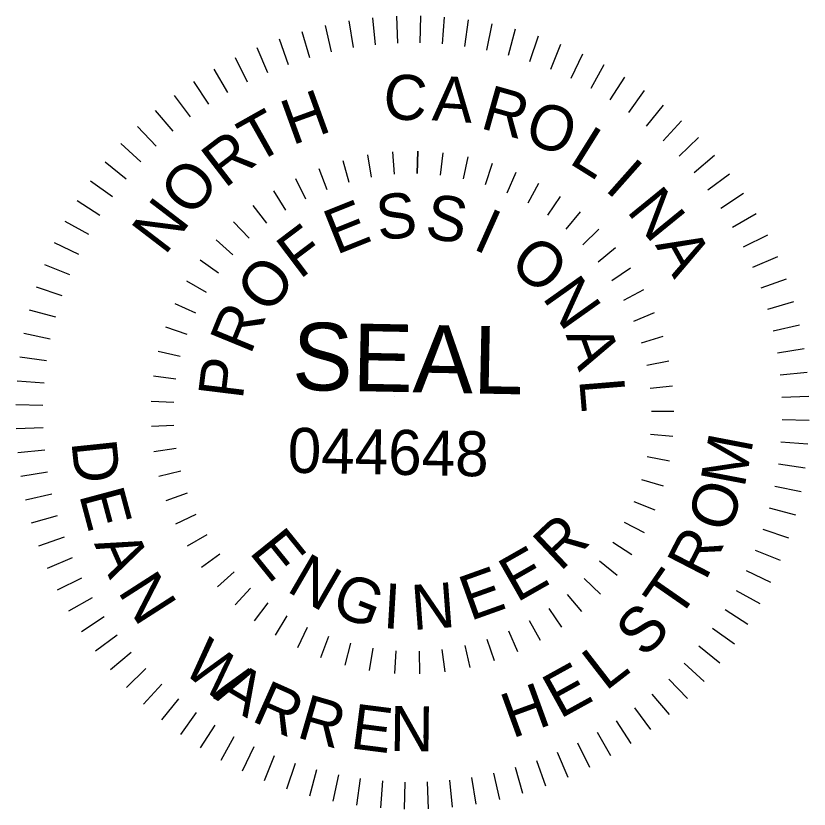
# Model space of a CAD drawing. Extents: x 0 to 2694, y -754 to 1499.
# Drawn here: x 3.3291 to 3.4509, y 1.8873 to 2.009 of the extents above; entities that cross this region are included whole.
import ezdxf

# ---------------------------------------------------------------- set-up
doc = ezdxf.new("R2010")
doc.units = 0
doc.layers.add('UBO Plan Sheet 34 CELL', color=7, linetype='Continuous')

msp = doc.modelspace()

# ---------------------------------------------------------------- linework, layer by layer
at = {"layer": 'UBO Plan Sheet 34 CELL'}
for p, q in [((3.38021, 2.00827), (3.38088, 2.00418)), ((3.38386, 2.00875), (3.38427, 2.00462)), ((3.38752, 2.00901), (3.38769, 2.00486)), ((3.3912, 2.00905), (3.39112, 2.0049)), ((3.39488, 2.00886), (3.39455, 2.00473)), ((3.39853, 2.00846), (3.39795, 2.00435)), ((3.37661, 2.00757), (3.37751, 2.00352)), ((3.40215, 2.00784), (3.40133, 2.00377)), ((3.40573, 2.00699), (3.40466, 2.00298)), ((3.37304, 2.00665), (3.3742, 2.00266)), ((3.40926, 2.00594), (3.40794, 2.00199)), ((3.36955, 2.00552), (3.37094, 2.00161)), ((3.4127, 2.00467), (3.41115, 2.00082)), ((3.36612, 2.00418), (3.36775, 2.00036)), ((3.36278, 2.00264), (3.36464, 1.99892)), ((3.41607, 2.00319), (3.4143, 1.99944)), ((3.41935, 2.00152), (3.41734, 1.99788)), ((3.35954, 2.00089), (3.36162, 1.9973)), ((3.35642, 1.99896), (3.35871, 1.9955)), ((3.42251, 1.99965), (3.42029, 1.99614)), ((3.42556, 1.99759), (3.42314, 1.99422)), ((3.35342, 1.99684), (3.35591, 1.99353)), ((3.42847, 1.99535), (3.42585, 1.99214)), ((3.35054, 1.99454), (3.35323, 1.99138)), ((3.43125, 1.99294), (3.42844, 1.98989)), ((3.34782, 1.99207), (3.35069, 1.98908)), ((3.43388, 1.99037), (3.43089, 1.9875)), ((3.34525, 1.98945), (3.34829, 1.98664)), ((3.38307, 1.98771), (3.38366, 1.9843)), ((3.38691, 1.98819), (3.38718, 1.98474)), ((3.39079, 1.9883), (3.39072, 1.98485)), ((3.39072, 1.98485), (3.39079, 1.9883)), ((3.39466, 1.98803), (3.39426, 1.9846)), ((3.43635, 1.98764), (3.43319, 1.98496)), ((3.34283, 1.98667), (3.34605, 1.98405)), ((3.37929, 1.98686), (3.38021, 1.98352)), ((3.39848, 1.9874), (3.39775, 1.98402)), ((3.40222, 1.9864), (3.40117, 1.9831)), ((3.37561, 1.98564), (3.37685, 1.98241)), ((3.37206, 1.98408), (3.3736, 1.98098)), ((3.40586, 1.98504), (3.40449, 1.98186)), ((3.43865, 1.98477), (3.43533, 1.98228)), ((3.3406, 1.98376), (3.34396, 1.98133)), ((3.40934, 1.98334), (3.40768, 1.98031)), ((3.36868, 1.98218), (3.37052, 1.97924)), ((3.44076, 1.98177), (3.43731, 1.97948)), ((3.33854, 1.98071), (3.34205, 1.97849)), ((3.41264, 1.98131), (3.41069, 1.97845)), ((3.3655, 1.97996), (3.36761, 1.97722)), ((3.41573, 1.97897), (3.41351, 1.97631)), ((3.4427, 1.97865), (3.43911, 1.97656)), ((3.33667, 1.97754), (3.34031, 1.97554)), ((3.36255, 1.97745), (3.36492, 1.97492)), ((3.41858, 1.97634), (3.41611, 1.97391)), ((3.44444, 1.9754), (3.44073, 1.97355)), ((3.335, 1.97426), (3.33875, 1.97249)), ((3.35985, 1.97466), (3.36245, 1.97238)), ((3.42116, 1.97345), (3.41848, 1.97127)), ((3.44598, 1.97207), (3.44217, 1.97044)), ((3.33352, 1.9709), (3.33737, 1.96935)), ((3.35744, 1.97163), (3.36024, 1.96961)), ((3.42346, 1.97032), (3.42058, 1.96841)), ((3.35533, 1.96838), (3.35832, 1.96663)), ((3.44733, 1.96864), (3.44342, 1.96725)), ((3.33225, 1.96745), (3.3362, 1.96614)), ((3.42543, 1.96699), (3.42238, 1.96537)), ((3.35354, 1.96494), (3.35668, 1.9635)), ((3.44846, 1.96515), (3.44447, 1.96399)), ((3.3312, 1.96392), (3.3352, 1.96286)), ((3.42709, 1.96348), (3.42389, 1.96216)), ((3.3521, 1.96134), (3.35537, 1.96021)), ((3.44937, 1.96158), (3.44533, 1.96068)), ((3.33035, 1.96035), (3.33442, 1.95952)), ((3.42839, 1.95983), (3.42507, 1.95883)), ((3.351, 1.95762), (3.35437, 1.95681)), ((3.45007, 1.95797), (3.44598, 1.95731)), ((3.32973, 1.95672), (3.33384, 1.95615)), ((3.42933, 1.95607), (3.42594, 1.95539)), ((3.35028, 1.95381), (3.3537, 1.95334)), ((3.45055, 1.95433), (3.44643, 1.95391)), ((3.32933, 1.95307), (3.33346, 1.95274)), ((3.42991, 1.95224), (3.42647, 1.95189)), ((3.34992, 1.94995), (3.35337, 1.9498)), ((3.38716, 1.95059), (3.38716, 1.95059)), ((3.45081, 1.95066), (3.44667, 1.9505)), ((3.32914, 1.9494), (3.33329, 1.94932)), ((3.43011, 1.94837), (3.42666, 1.94835)), ((3.34993, 1.94608), (3.35338, 1.94626)), ((3.45085, 1.94699), (3.4467, 1.94707)), ((3.32918, 1.94572), (3.33332, 1.94589)), ((3.42994, 1.94449), (3.4265, 1.94481)), ((3.35033, 1.94222), (3.35374, 1.94274)), ((3.45067, 1.94331), (3.44653, 1.94364)), ((3.32944, 1.94205), (3.33357, 1.94247)), ((3.42602, 1.94143), (3.42942, 1.94078)), ((3.45026, 1.93966), (3.44616, 1.94024)), ((3.32992, 1.93841), (3.33401, 1.93907)), ((3.35109, 1.93842), (3.35444, 1.93926)), ((3.42849, 1.93688), (3.42517, 1.93786)), ((3.44964, 1.93604), (3.44558, 1.93686)), ((3.33062, 1.9348), (3.33467, 1.93571)), ((3.35221, 1.93471), (3.35547, 1.93587)), ((3.42722, 1.93322), (3.42401, 1.93451)), ((3.4488, 1.93246), (3.44479, 1.93353)), ((3.33153, 1.93124), (3.33553, 1.93239)), ((3.35369, 1.93113), (3.35682, 1.9326)), ((3.42559, 1.92971), (3.42253, 1.9313)), ((3.33267, 1.92774), (3.33658, 1.92914)), ((3.3555, 1.92771), (3.35848, 1.92947)), ((3.44774, 1.92893), (3.4438, 1.93025)), ((3.42365, 1.92636), (3.42075, 1.92823)), ((3.44647, 1.92549), (3.44262, 1.92704)), ((3.33401, 1.92432), (3.33782, 1.92594)), ((3.35764, 1.92447), (3.36043, 1.92651)), ((3.42139, 1.9232), (3.41868, 1.92536)), ((3.36009, 1.92146), (3.36266, 1.92376)), ((3.44499, 1.92212), (3.44125, 1.92389)), ((3.33555, 1.92098), (3.33926, 1.92283)), ((3.41882, 1.9203), (3.41634, 1.9227)), ((3.3628, 1.9187), (3.36515, 1.92124)), ((3.44332, 1.91884), (3.43969, 1.92084)), ((3.33729, 1.91774), (3.34088, 1.91982)), ((3.416, 1.91764), (3.41376, 1.92028)), ((3.36578, 1.91621), (3.36786, 1.91897)), ((3.36898, 1.91402), (3.37079, 1.91697)), ((3.41293, 1.91528), (3.41095, 1.91811)), ((3.44145, 1.91567), (3.43795, 1.9179)), ((3.33923, 1.91461), (3.34269, 1.9169)), ((3.40965, 1.91322), (3.40795, 1.91623)), ((3.37238, 1.91216), (3.3739, 1.91526)), ((3.40618, 1.91149), (3.40478, 1.91465)), ((3.43939, 1.91263), (3.43603, 1.91505)), ((3.34135, 1.91161), (3.34466, 1.9141)), ((3.37594, 1.91062), (3.37715, 1.91386)), ((3.40256, 1.91009), (3.40147, 1.91338)), ((3.3805, 1.91278), (3.3796, 1.90944)), ((3.39882, 1.90906), (3.39806, 1.91244)), ((3.43716, 1.90972), (3.43394, 1.91233)), ((3.34365, 1.90874), (3.34681, 1.91143)), ((3.38342, 1.90862), (3.38398, 1.91203)), ((3.38727, 1.90817), (3.3875, 1.91162)), ((3.39114, 1.90809), (3.39105, 1.91155)), ((3.395, 1.90839), (3.39457, 1.91182)), ((3.43475, 1.90693), (3.4317, 1.90975)), ((3.34611, 1.90602), (3.3491, 1.90889)), ((3.43217, 1.90431), (3.4293, 1.9073)), ((3.34874, 1.90344), (3.35155, 1.90649)), ((3.42945, 1.90184), (3.42676, 1.905)), ((3.35152, 1.90103), (3.35414, 1.90424)), ((3.42657, 1.89954), (3.42409, 1.90286)), ((3.35443, 1.89879), (3.35686, 1.90216)), ((3.35748, 1.89674), (3.3597, 1.90024)), ((3.42357, 1.89742), (3.42129, 1.90088)), ((3.42045, 1.89549), (3.41837, 1.89908)), ((3.36065, 1.89487), (3.36265, 1.8985)), ((3.41721, 1.89374), (3.41535, 1.89746)), ((3.36392, 1.8932), (3.3657, 1.89694)), ((3.36729, 1.89172), (3.36884, 1.89557)), ((3.41387, 1.89221), (3.41225, 1.89602)), ((3.37074, 1.89045), (3.37205, 1.89439)), ((3.41045, 1.89086), (3.40905, 1.89477)), ((3.37427, 1.88939), (3.37533, 1.8934)), ((3.37784, 1.88855), (3.37867, 1.89261)), ((3.40339, 1.88881), (3.40248, 1.89286)), ((3.40695, 1.88973), (3.4058, 1.89372)), ((3.38146, 1.88793), (3.38204, 1.89203)), ((3.38512, 1.88752), (3.38545, 1.89166)), ((3.38879, 1.88734), (3.38887, 1.89149)), ((3.39247, 1.88738), (3.3923, 1.89152)), ((3.39614, 1.88764), (3.39572, 1.89176)), ((3.39978, 1.88811), (3.39911, 1.89221))]:
    msp.add_line(p, q, dxfattribs=at)

# ---------------------------------------------------------------- texts
for s, height, rotation, p in [('C', 0.00691, 356.2217, (3.38536, 1.99332)), ('A', 0.00691, 356.2217, (3.39291, 1.99303)), ('H', 0.00691, 19.9324, (3.37153, 1.98915)), ('R', 0.00691, 344.2124, (3.40021, 1.99187)), ('T', 0.00691, 29.3644, (3.36591, 1.98625)), ('O', 0.00691, 341.1556, (3.40686, 1.98975)), ('L', 0.00691, 328.0193, (3.41383, 1.98653)), ('R', 0.00691, 37.5253, (3.36118, 1.98248)), ('O', 0.00691, 50.5821, (3.35609, 1.97793)), ('I', 0.00691, 318.4439, (3.41932, 1.98241)), ('N', 0.00691, 309.1494, (3.42272, 1.97908)), ('S', 0.00691, 6.5129, (3.38482, 1.97457)), ('S', 0.00691, 351.2166, (3.39173, 1.97501)), ('N', 0.00691, 52.5415, (3.352, 1.97217)), ('E', 0.00691, 21.8091, (3.37828, 1.97233)), ('I', 0.00691, 335.9204, (3.39904, 1.97337)), ('F', 0.00691, 37.1054, (3.37268, 1.96853)), ('O', 0.00691, 320.6242, (3.40456, 1.97057)), ('A', 0.00691, 299.3819, (3.42717, 1.97389)), ('O', 0.00691, 52.4016, (3.36797, 1.96305)), ('N', 0.00691, 305.3279, (3.40979, 1.96584)), ('R', 0.00691, 67.6979, (3.36512, 1.9569)), ('SEAL', 0.010372, 358.8648, (3.37148, 1.95167)), ('A', 0.00691, 290.0317, (3.41347, 1.96011)), ('P', 0.00691, 82.9941, (3.36394, 1.95007)), ('L', 0.00691, 274.7354, (3.41557, 1.95322)), ('044648', 0.006909, 358.8648, (3.3708, 1.93897)), ('M', 0.00691, 79.1773, (3.44092, 1.9365)), ('D', 0.00691, 275.9811, (3.33765, 1.94369)), ('E', 0.00691, 284.9836, (3.33881, 1.93559)), ('O', 0.00691, 71.1829, (3.43854, 1.92947)), ('R', 0.00691, 43.4297, (3.41266, 1.92366)), ('E', 0.00691, 308.9349, (3.3648, 1.92674)), ('R', 0.00691, 62.7337, (3.43493, 1.92224)), ('A', 0.00691, 293.8062, (3.34111, 1.92807)), ('E', 0.00691, 29.6586, (3.40598, 1.91897)), ('N', 0.00691, 329.7899, (3.37049, 1.92087)), ('E', 0.00691, 19.6727, (3.39884, 1.91617)), ('T', 0.00691, 55.228, (3.43075, 1.91616)), ('N', 0.00691, 302.6889, (3.34467, 1.92073)), ('G', 0.00691, 338.5562, (3.37719, 1.9175)), ('I', 0.00691, 356.651, (3.38537, 1.91512)), ('N', 0.00691, 4.2806, (3.39006, 1.9148)), ('S', 0.00691, 46.5552, (3.42561, 1.91036)), ('W', 0.00691, 320.3641, (3.35443, 1.90863)), ('L', 0.00691, 37.7626, (3.41962, 1.90535)), ('E', 0.00691, 28.88, (3.41262, 1.90112)), ('A', 0.00691, 329.3125, (3.35938, 1.90437)), ('R', 0.00691, 336.0279, (3.3651, 1.90094)), ('H', 0.00691, 19.9974, (3.40529, 1.89814)), ('R', 0.00691, 343.8077, (3.37203, 1.89841)), ('E', 0.00691, 352.7158, (3.38031, 1.89669)), ('N', 0.00691, 359.3001, (3.38651, 1.89626))]:
    msp.add_text(s, height=height, rotation=rotation, dxfattribs=at).set_placement(p)

doc.saveas('drawing.dxf')
